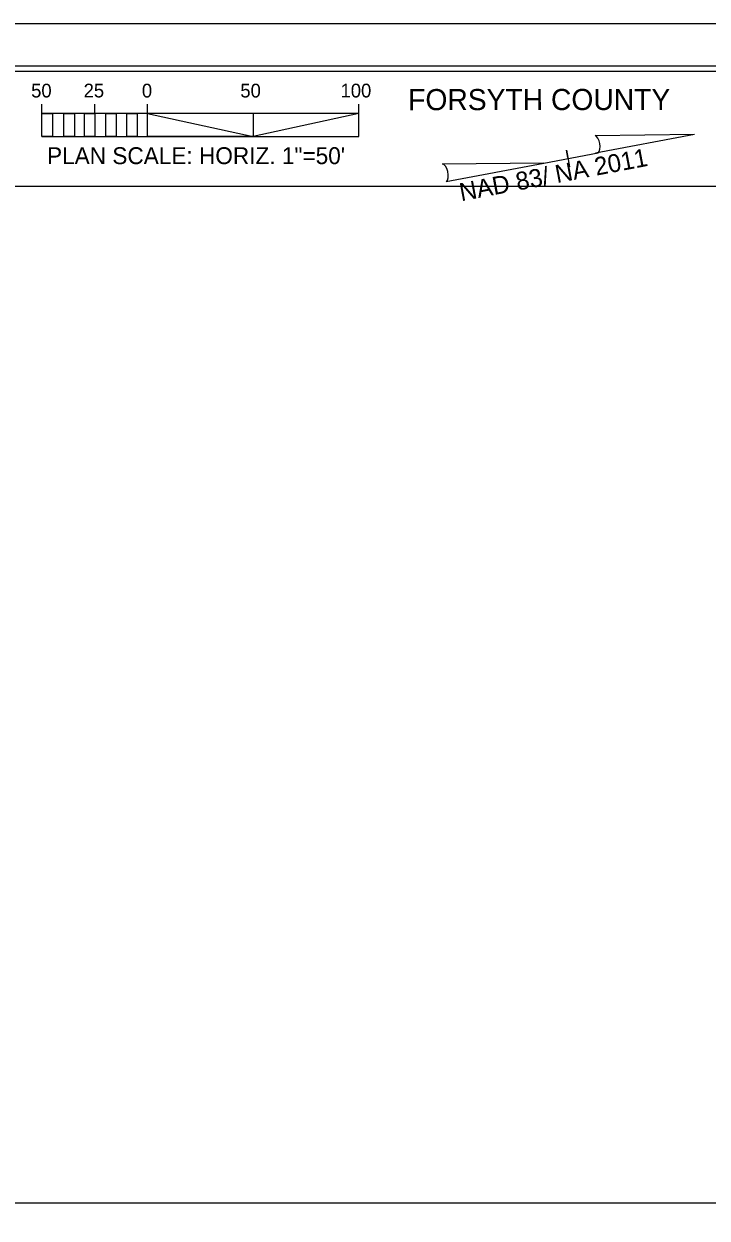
# Model space of a CAD drawing. Extents: x 0 to 2694, y -754 to 1499.
# Drawn here: x 1.849 to 2.388, y 0.891 to 1.833 of the extents above; entities that cross this region are included whole.
import ezdxf

# ---------------------------------------------------------------- set-up
doc = ezdxf.new("R2010")
doc.units = 0
for name, color, linetype in [('Scratch_Level_3', 7, 'Continuous'), ('UC Notes and Details Sheet 34 CELL', 7, 'Continuous'), ('UC Plan Profile Sheet 34 CELL', 7, 'Continuous'), ('UC Title Plan Sheet 34 CELL', 7, 'Continuous')]:
    doc.layers.add(name, color=color, linetype=linetype)

msp = doc.modelspace()

# ---------------------------------------------------------------- linework, layer by layer
at = {"layer": 'Scratch_Level_3'}
msp.add_lwpolyline([(0.39416, 0.90275), (0.39416, 1.70532), (2.47076, 1.70532), (2.47076, 1.49375), (2.76084, 1.49375), (2.76084, 0.90275)], close=True, dxfattribs=at)
at = {"layer": 'UC Notes and Details Sheet 34 CELL'}
for p, q in [((2.2997, 1.74522), (2.37814, 1.74618)), ((2.37816, 1.7461), (2.29988, 1.73126)), ((2.37816, 1.7461), (2.37817, 1.74602)), ((2.37816, 1.7461), (2.37817, 1.74602)), ((2.25928, 1.72355), (2.30218, 1.73169)), ((2.27703, 1.73371), (2.27701, 1.73379)), ((2.27813, 1.72789), (2.27703, 1.73371)), ((2.27704, 1.73362), (2.27953, 1.72052)), ((2.29988, 1.73126), (2.3021, 1.73167)), ((2.25928, 1.72355), (2.17931, 1.72256)), ((2.18225, 1.70886), (2.25928, 1.72355))]:
    msp.add_line(p, q, dxfattribs=at)
for centre, start_param, end_param in [((2.30017, 1.73829), 0.216388, 2.908219), ((2.18036, 1.71557), 0.201328, 3.141593)]:
    msp.add_ellipse(centre, major_axis=(0.00126, -0.00694), ratio=0.461098, start_param=start_param, end_param=end_param, dxfattribs=at)
at = {"layer": 'UC Plan Profile Sheet 34 CELL'}
for points in [[(0.02749, 0.00833), (2.83333, 0.00833), (2.83333, 1.83333), (0.02749, 1.83333)], [(0.04916, 0.04166), (2.82583, 0.04166), (2.82583, 1.8), (0.04916, 1.8)], [(2.80499, 1.79583), (0.30499, 1.79583), (0.30499, 0.04583), (2.80499, 0.04583)]]:
    msp.add_lwpolyline(points, close=True, dxfattribs=at)
at = {"layer": 'UC Title Plan Sheet 34 CELL'}
for p, q in [((1.86331, 1.74454), (1.86331, 1.76987)), ((2.11331, 1.76263), (1.86331, 1.76264)), ((1.90498, 1.76264), (1.90498, 1.7699)), ((1.92189, 1.76266), (1.92189, 1.74454)), ((1.94665, 1.76264), (1.94665, 1.76988)), ((2.02998, 1.76266), (2.02998, 1.74455)), ((2.11331, 1.76266), (2.11331, 1.76991)), ((2.11331, 1.74453), (2.11331, 1.76266)), ((1.86331, 1.74453), (2.11331, 1.74454))]:
    msp.add_line(p, q, dxfattribs=at)
for points in [[(1.86331, 1.76264), (1.87157, 1.76264), (1.87157, 1.74453), (1.86331, 1.74453)], [(1.88063, 1.76266), (1.88888, 1.76264), (1.88888, 1.74453), (1.88065, 1.74453)], [(1.89673, 1.76264), (1.90498, 1.76264), (1.90498, 1.74455), (1.89673, 1.74455)], [(1.91364, 1.76264), (1.92189, 1.76266), (1.92189, 1.74454), (1.91364, 1.74454)], [(1.93014, 1.76266), (1.93839, 1.76266), (1.9384, 1.74453), (1.93014, 1.74454)], [(1.94665, 1.76264), (2.02998, 1.74455), (1.94665, 1.74453)], [(2.11331, 1.76266), (2.02998, 1.74455), (2.11331, 1.74453)]]:
    msp.add_lwpolyline(points, close=True, dxfattribs=at)

# ---------------------------------------------------------------- texts
at = {"layer": 'UC Notes and Details Sheet 34 CELL'}
msp.add_text('NAD 83/ NA 2011', height=0.0141667, rotation=10.73754, dxfattribs=at).set_placement((2.19404, 1.69334))
at = {"layer": 'UC Plan Profile Sheet 34 CELL'}
msp.add_text('FORSYTH COUNTY', height=0.0166667, rotation=0.04517, dxfattribs=at).set_placement((2.15218, 1.76522))
at = {"layer": 'UC Title Plan Sheet 34 CELL'}
for s, height, p in [('50', 0.010867, (1.85475, 1.77525)), ('25', 0.010867, (1.89615, 1.77527)), ('0', 0.01087, (1.94211, 1.77525)), ('50', 0.010867, (2.01979, 1.77525)), ('100', 0.010867, (2.09884, 1.77527)), ('PLAN SCALE: HORIZ. 1"=50\'', 0.0133333, (1.86726, 1.72266))]:
    msp.add_text(s, height=height, rotation=0.00136, dxfattribs=at).set_placement(p)

doc.saveas('drawing.dxf')
